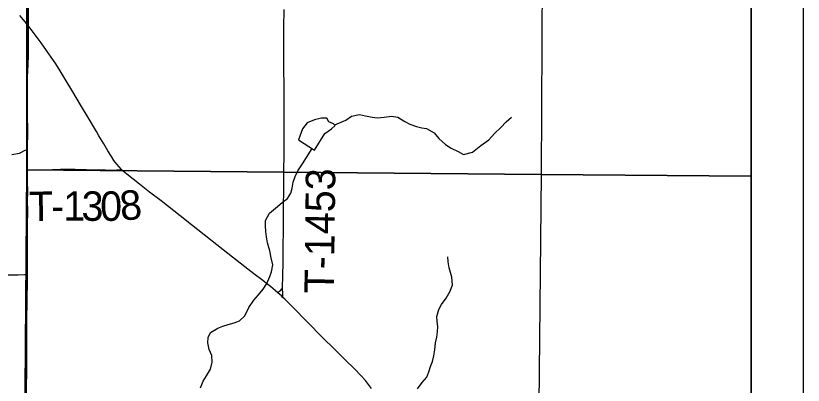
# Model space of a CAD drawing. Extents: x 0 to 34, y 0 to 22.
# Drawn here: x 7.484 to 9, y 15.879 to 16.591 of the extents above; entities that cross this region are included whole.
import ezdxf

# ---------------------------------------------------------------- set-up
doc = ezdxf.new("R2010")
doc.units = 0
for name, color, linetype in [('Default', 7, 'Continuous'), ('GM_X_Minor_Lake', 7, 'Continuous'), ('GM_X_Minor_River', 7, 'Continuous'), ('GM_X_Section', 7, 'Continuous'), ('GM_X_State_Route', 7, 'Continuous'), ('GM_X_Township_Road', 7, 'Continuous'), ('GM_X_Township_Road_Text', 7, 'Continuous'), ('SH_Cut_Line', 7, 'Continuous'), ('SH_Data', 7, 'Continuous')]:
    doc.layers.add(name, color=color, linetype=linetype)

msp = doc.modelspace()

# ---------------------------------------------------------------- linework, layer by layer
at = {"layer": 'Default'}
for points in [[(8.9, 14.1), (8.9, 18.2728)], [(7.5053, 17.3084), (7.5076, 16.5733), (7.5075, 16.5597), (7.5075, 16.5286), (7.5077, 16.5193), (7.5076, 16.5132), (7.5071, 16.4978), (7.5064, 16.4853), (7.5056, 16.4721), (7.5054, 16.461), (7.5058, 16.4432), (7.5059, 16.4113), (7.5059, 16.3892), (7.5062, 16.3799), (7.506, 16.3713), (7.5062, 16.3589), (7.5059, 16.3453), (7.5059, 16.3304), (7.5056, 16.3179), (7.5058, 16.2947), (7.5056, 16.2714), (7.5061, 16.2527), (7.5059, 16.2341), (7.5062, 16.2155), (7.5058, 16.1876), (7.5059, 16.1721), (7.5057, 16.1473), (7.5056, 16.11), (7.5056, 16.0932), (7.5056, 16.082), (7.5045, 16.0043), (7.5041, 15.9172), (7.5038, 15.8644)], [(7.5038, 15.8644), (7.5041, 15.9172), (7.5045, 16.0043), (7.5056, 16.082), (7.5056, 16.0932), (7.5056, 16.11), (7.5057, 16.1473), (7.5059, 16.1721), (7.5058, 16.1876), (7.5062, 16.2155), (7.5059, 16.2341), (7.5061, 16.2527), (7.5056, 16.2714), (7.5058, 16.2947), (7.5056, 16.3179), (7.5059, 16.3304), (7.5059, 16.3453), (7.5062, 16.3589), (7.506, 16.3713), (7.5062, 16.3799), (7.5059, 16.3892), (7.5059, 16.4113), (7.5058, 16.4432), (7.5054, 16.461), (7.5056, 16.4721), (7.5064, 16.4853), (7.5071, 16.4978), (7.5076, 16.5132), (7.5077, 16.5193), (7.5075, 16.5286), (7.5075, 16.5597), (7.5076, 16.5733), (7.5053, 17.3084)]]:
    msp.add_lwpolyline(points, dxfattribs=at)
for points in [[(8.9, 16.282), (8.9, 17.2976), (8.5004, 17.303), (8.4953, 16.2856)], [(8.9, 15.267), (8.9, 16.282), (8.4953, 16.2856), (8.4854, 15.2725)]]:
    msp.add_lwpolyline(points, close=True, dxfattribs=at)
at = {"layer": 'GM_X_Minor_Lake'}
for points in [[(8.0586, 16.3324), (8.0787, 16.3643), (8.0914, 16.3734), (8.0988, 16.38), (8.0957, 16.3833), (8.0865, 16.3869), (8.0826, 16.394), (8.0724, 16.3938), (8.0588, 16.3908), (8.0449, 16.3848), (8.0357, 16.3732), (8.0279, 16.3521)], [(8.0279, 16.3521), (8.0586, 16.3324)]]:
    msp.add_lwpolyline(points, dxfattribs=at)
at = {"layer": 'GM_X_Minor_River'}
for points in [[(8.0979, 16.381), (8.1194, 16.3903), (8.1299, 16.3978), (8.1453, 16.4012), (8.1571, 16.3985), (8.1701, 16.3961), (8.1803, 16.3948), (8.1932, 16.3959), (8.2072, 16.3981), (8.2193, 16.3961), (8.2328, 16.3873), (8.2424, 16.3826), (8.2554, 16.378), (8.2653, 16.3756), (8.2748, 16.3743), (8.2894, 16.3659), (8.298, 16.3547), (8.3111, 16.3433), (8.3219, 16.336), (8.3357, 16.3295), (8.346, 16.324), (8.363, 16.3286), (8.379, 16.3411), (8.3943, 16.3521), (8.4057, 16.3641), (8.4176, 16.3762), (8.4279, 16.387), (8.438, 16.396)], [(7.4764, 16.3241), (7.4908, 16.3268), (7.503, 16.3332)], [(7.8393, 15.8744), (7.8447, 15.8875), (7.8509, 15.8975), (7.8585, 15.9102), (7.862, 15.9239), (7.8609, 15.9364), (7.8561, 15.9484), (7.8536, 15.9613), (7.8544, 15.9716), (7.8584, 15.9811), (7.8726, 15.9894), (7.8827, 15.9935), (7.8929, 15.9964), (7.9042, 15.9997), (7.9147, 16.0033), (7.9247, 16.0131), (7.9327, 16.0292), (7.9422, 16.0435), (7.9511, 16.0539), (7.9599, 16.0648), (7.9672, 16.0752), (7.973, 16.0886), (7.9758, 16.0981), (7.9785, 16.1111), (7.9752, 16.1251), (7.9726, 16.1383), (7.9684, 16.1538), (7.9667, 16.1651), (7.9653, 16.1753), (7.9643, 16.1863), (7.9648, 16.1966), (7.9724, 16.2108), (7.9836, 16.2205), (7.9966, 16.2315), (8.007, 16.2393), (8.0136, 16.2493), (8.016, 16.2589), (8.018, 16.2707), (8.0216, 16.2814), (8.027, 16.2925), (8.0361, 16.306), (8.0434, 16.3183), (8.0541, 16.3353)], [(8.296, 15.982), (8.2962, 15.9923), (8.2948, 16.0021), (8.2946, 16.012), (8.2984, 16.0254), (8.3035, 16.035), (8.3127, 16.0473), (8.3203, 16.0608), (8.3246, 16.073), (8.3235, 16.0874), (8.3185, 16.1055), (8.3164, 16.1172), (8.3158, 16.1271)], [(8.2573, 15.8726), (8.2661, 15.8849), (8.2753, 15.895), (8.2792, 15.905), (8.282, 15.9153), (8.286, 15.9253), (8.2887, 15.936), (8.2908, 15.9474), (8.292, 15.9611), (8.2943, 15.9721), (8.296, 15.982)]]:
    msp.add_lwpolyline(points, dxfattribs=at)
at = {"layer": 'GM_X_Section'}
for points in [[(7.5048, 17.3031), (8.5004, 17.303), (8.4953, 16.2856), (7.5047, 16.2943)], [(7.5047, 16.2943), (8.4953, 16.2856), (8.4854, 15.2725), (7.4976, 15.2767)]]:
    msp.add_lwpolyline(points, close=True, dxfattribs=at)
at = {"layer": 'GM_X_State_Route'}
for points in [[(7.5078, 16.5727), (7.5017, 16.5795), (7.4918, 16.5919)], [(8.1684, 15.8734), (8.163, 15.881), (8.1571, 15.8883), (8.1488, 15.8977), (8.1358, 15.911), (8.118, 15.9285), (8.0981, 15.948), (8.0739, 15.9722), (8.0172, 16.0297), (8.0018, 16.0451), (7.998, 16.0487), (7.9951, 16.0515), (7.9884, 16.0574), (7.9834, 16.0618), (7.9739, 16.0697), (7.9666, 16.0755), (7.9591, 16.0811), (7.9418, 16.0942), (7.9246, 16.1075), (7.8831, 16.1401), (7.8466, 16.1691), (7.8222, 16.1883), (7.8003, 16.2057), (7.7636, 16.2344), (7.7415, 16.2515), (7.7217, 16.2666), (7.6974, 16.286), (7.6909, 16.2915), (7.6872, 16.2948), (7.6783, 16.3051), (7.6727, 16.3127), (7.6679, 16.32), (7.6612, 16.331), (7.6533, 16.3444), (7.6439, 16.3602), (7.6392, 16.3683), (7.6229, 16.3953), (7.6102, 16.4166), (7.5914, 16.448), (7.5788, 16.4693), (7.5691, 16.4853), (7.5606, 16.4984), (7.543, 16.524), (7.5326, 16.5394), (7.5078, 16.5727)]]:
    msp.add_lwpolyline(points, dxfattribs=at)
at = {"layer": 'GM_X_Township_Road'}
for points in [[(7.9976, 16.0667), (7.998, 16.0908), (7.9984, 16.1156), (7.9985, 16.1467), (7.999, 16.1777), (7.9991, 16.1964), (7.9995, 16.2212), (8, 16.2585), (8.0001, 16.2833), (8.0002, 16.333), (8.0004, 16.3764), (8.0002, 16.451), (8.0001, 16.4944), (7.9999, 16.5131), (7.9998, 16.5224), (7.9998, 16.5472), (7.9999, 16.5689), (8.0002, 16.603)], [(7.506, 16.2942), (7.5058, 16.3174), (7.5061, 16.3298), (7.5061, 16.3447), (7.5064, 16.3584), (7.5062, 16.3708), (7.5064, 16.3794), (7.5062, 16.3887), (7.5061, 16.4108), (7.506, 16.4426), (7.5056, 16.4605), (7.5058, 16.4715), (7.5067, 16.4848), (7.5073, 16.4972), (7.5078, 16.5126), (7.5079, 16.5188), (7.5077, 16.528), (7.5077, 16.5592), (7.5078, 16.5727)], [(7.5058, 16.0927), (7.5058, 16.1094), (7.5059, 16.1467), (7.5061, 16.1716), (7.506, 16.1871), (7.5064, 16.215), (7.5061, 16.2336), (7.5063, 16.2522), (7.5059, 16.2708), (7.506, 16.2942)], [(7.506, 16.2942), (7.5182, 16.2944), (7.5389, 16.2946), (7.5697, 16.2954), (7.5841, 16.2958), (7.598, 16.2955), (7.6191, 16.2948), (7.6346, 16.2943), (7.6565, 16.2943), (7.6687, 16.294), (7.678, 16.2943), (7.6872, 16.2948)], [(6.9962, 16.0884), (7.0036, 16.0881), (7.0097, 16.0879), (7.0283, 16.0873), (7.0718, 16.0872), (7.1371, 16.0882), (7.1807, 16.0884), (7.2989, 16.0896), (7.4138, 16.0907), (7.4417, 16.0914), (7.4665, 16.0918), (7.4881, 16.0924), (7.5004, 16.0927), (7.5058, 16.0927)], [(7.504, 15.8638), (7.5043, 15.9167), (7.5048, 16.0037), (7.5058, 16.0815), (7.5058, 16.0927)], [(7.9884, 16.0574), (7.9918, 16.0608), (7.9939, 16.0629), (7.9961, 16.0652), (7.9976, 16.0667)], [(7.998, 16.0487), (7.9979, 16.0567), (7.9976, 16.066), (7.9976, 16.0667)]]:
    msp.add_lwpolyline(points, dxfattribs=at)
at = {"layer": 'SH_Cut_Line'}
for points in [[(8.9, 14.1), (8.9, 20.9)], [(7.5038, 15.8644), (7.5041, 15.9172), (7.5045, 16.0043), (7.5056, 16.082), (7.5056, 16.0932), (7.5056, 16.11), (7.5057, 16.1473), (7.5059, 16.1721), (7.5058, 16.1876), (7.5062, 16.2155), (7.5059, 16.2341), (7.5061, 16.2527), (7.5056, 16.2714), (7.5058, 16.2947), (7.5056, 16.3179), (7.5059, 16.3304), (7.5059, 16.3453), (7.5062, 16.3589), (7.506, 16.3713), (7.5062, 16.3799), (7.5059, 16.3892), (7.5059, 16.4113), (7.5058, 16.4432), (7.5054, 16.461), (7.5056, 16.4721), (7.5064, 16.4853), (7.5071, 16.4978), (7.5076, 16.5132), (7.5077, 16.5193), (7.5075, 16.5286), (7.5075, 16.5597), (7.5076, 16.5733), (7.5053, 17.3084)], [(7.5053, 17.3084), (7.5076, 16.5733), (7.5075, 16.5597), (7.5075, 16.5286), (7.5077, 16.5193), (7.5076, 16.5132), (7.5071, 16.4978), (7.5064, 16.4853), (7.5056, 16.4721), (7.5054, 16.461), (7.5058, 16.4432), (7.5059, 16.4113), (7.5059, 16.3892), (7.5062, 16.3799), (7.506, 16.3713), (7.5062, 16.3589), (7.5059, 16.3453), (7.5059, 16.3304), (7.5056, 16.3179), (7.5058, 16.2947), (7.5056, 16.2714), (7.5061, 16.2527), (7.5059, 16.2341), (7.5062, 16.2155), (7.5058, 16.1876), (7.5059, 16.1721), (7.5057, 16.1473), (7.5056, 16.11), (7.5056, 16.0932), (7.5056, 16.082), (7.5045, 16.0043), (7.5041, 15.9172), (7.5038, 15.8644)]]:
    msp.add_lwpolyline(points, dxfattribs=at)
at = {"layer": 'SH_Data'}
for p, q in [((9, 21), (9, 14)), ((8.9, 20.9), (8.9, 14.1))]:
    msp.add_line(p, q, dxfattribs=at)

# ---------------------------------------------------------------- texts
at = {"layer": 'GM_X_Township_Road_Text'}
for s, height, rotation, p in [('T-1453', 0.05682, 89.3073, (8.0962, 16.0562)), ('8', 0.0568, 5.1576, (7.6865, 16.1964)), ('T', 0.0568, 1.1743, (7.5097, 16.1953)), ('1', 0.0568, 359.9532, (7.5752, 16.1965)), ('3', 0.0568, 359.0372, (7.6099, 16.1965)), ('0', 0.0568, 0.4565, (7.6464, 16.1959)), ('-', 0.0568, 0.7572, (7.552, 16.1962))]:
    msp.add_text(s, height=height, rotation=rotation, dxfattribs=at).set_placement(p)

doc.saveas('drawing.dxf')
